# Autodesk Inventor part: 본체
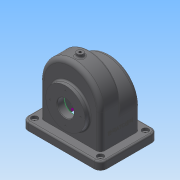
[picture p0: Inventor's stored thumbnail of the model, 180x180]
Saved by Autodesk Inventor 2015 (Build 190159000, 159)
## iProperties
Created: 2017-11
Part Number: 본체
Material: 알루미늄 6061
Document SubType Name: Modeling
Designer: user
Density: 2.7 g/cm^3
Appearance: 연회색
Mass: 1083.79 g
Surface Area: 1185.38 cm^2
Volume: 401.404 cm^3
Author: user
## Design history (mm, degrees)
sketch "스케치1"
  geometry: L1 (-58, 15)-(-58, -65); L2 (-58, -65)-(58, -65); L3 (58, -65)-(58, 15); C1 r 37.5 at (0, 0); A1 r 58 centre (0, 15) between (58, 15) and (-58, 15)
  constraints: 6 end point, 2 centre point, 2 point on circle, 1 perpendicular, 1 tangent, 1 vertical
extrude "돌출1" new body sketch "스케치1" distance "d18" = 9; taper "d19" = 0 deg
extrude "돌출2" join sketch "스케치1" distance "d20" = 38; taper "d21" = 0 deg
node "작업 평면1"
sketch "스케치2"
  geometry: C1 r 31 at (0, 0); 1 further point
  constraints: 1 centre point, 1 coincident
extrude "돌출3" join sketch "스케치2" distance "d30" = 10; taper "d31" = 0 deg
sketch "스케치3"
  geometry: L1 (58, -8)-(58, -65); L2 (58, -65)-(-58, -65); L3 (-58, -65)-(-58, -8); A1 r 58 centre (0, -8) between (58, -8) and (-58, -8); 1 further point
  constraints: 6 end point, 2 point on circle, 1 centre point, 1 perpendicular, 1 vertical
extrude "돌출4" join sketch "스케치3" distance "d39" = 38; taper "d40" = 0 deg
sketch "스케치4"
  geometry: C1 r 37.5 at (0, 0) reference; C2 r 16 at (0, 0)
  constraints: 1 centre point, 1 coincident
  dimensions: "d41" = 32 diameter of C2
extrude "돌출5" cut sketch "스케치4" distance "d42" = 14; taper "d43" = 0 deg
sketch "스케치5"
  geometry: L1 (-53, 14.446)-(-53, -65.554); L2 (53, 14.446)-(53, -65.554); L3 (-53, -65.554)-(53, -65.554); C1 r 16 at (0, 0) reference; A1 r 53 centre (0, 14.446) between (53, 14.446) and (-53, 14.446); A2 r 53 centre (0, -8.554) between (53, -8.554) and (-53, -8.554)
  constraints: 6 end point, 4 point on circle, 2 centre point, 2 point on line, 2 tangent, 2 vertical, 1 horizontal
extrude "돌출6" cut sketch "스케치5" distance "d49" = 66; taper "d50" = 0 deg
extrude "돌출7" cut sketch "스케치5" distance "d51" = 28; taper "d52" = 0 deg
extrude "돌출8" cut sketch "스케치5" distance "d53" = 95; taper "d54" = 0 deg
sketch "스케치6"
  geometry: L1 (133, 17)-(-17, 17); L2 (-17, 17)-(-17, -93); L3 (-17, -93)-(133, -93); L4 (133, 17)-(133, -93); L5 (-17, 17)-(-17, 5); L6 (-17, 17)-(-5, 17); L7 (133, -93)-(133, -81); L8 (133, -93)-(121, -93); L9 (116, 0)-(0, 0); L10 (0, 0)-(0, -76); L11 (0, -76)-(116, -76); L12 (116, -76)-(116, 0); L13 (111, -5)-(5, -5); L14 (5, -5)-(5, -71); L15 (5, -71)-(111, -71); L16 (111, -71)-(111, -5); C1 r 6 at (121, 5); C2 r 6 at (121, -81); C3 r 6 at (-5, -81); C4 r 6 at (-5, 5); C5 r 2.5 at (121, 5); C6 r 2.5 at (121, -81); C7 r 2.5 at (-5, -81); C8 r 2.5 at (-5, 5); 1 further point
  constraints: 32 end point, 8 centre point, 4 coincident, 4 parallel, 4 point on line, 3 perpendicular, 2 horizontal, 1 vertical
  dimensions: "d69" = 5 diameter of C5; "d70" = 5 diameter of C6; "d71" = 5 diameter of C7; "d72" = 5 diameter of C8
extrude "돌출15" join sketch "스케치6" distance "d86" = 15; taper "d87" = 0 deg
extrude "돌출16" join sketch "스케치6" distance "d88" = 10; taper "d89" = 0 deg
extrude "돌출17" join sketch "스케치6" distance "d90" = 10; taper "d91" = 0 deg
node "작업 평면3"
sketch "스케치8"
  geometry: C1 r 6 at (75, -36); 1 further point
  constraints: 1 centre point
  dimensions: "d95" = 12 diameter of C1
extrude "돌출18" join sketch "스케치8" stored distance "d96" = 0; taper "d97" = 0 deg
hole "구멍1" sketch "스케치8" diameter "d98" = 4.459; stored, may be unused: countersink angle "d102" = 82 deg, drill point angle "d104" = 118 deg; dims "d99" = 10, "d100" = 3.023, "d101" = 2, "d103" = 12.8
sketch "스케치9"
  geometry: L1 (0, 29)-(0, -29); L2 (-29, 0)-(29, 0); C1 r 37.5 at (0, 0) reference; A1 r 29 centre (0, 0) between (0, 29) and (0, -29)
  constraints: 4 end point, 4 point on circle, 1 centre point, 1 coincident, 1 perpendicular, 1 vertical
  dimensions: "d105" = 58 diameter of A1
hole "구멍2" sketch "스케치9" at (0, 29), (-29, 0), (29, 0), (0, -29) diameter "d106" = 2.459; stored, may be unused: countersink angle "d110" = 82 deg, drill point angle "d112" = 118 deg; dims "d107" = 6, "d108" = 3.023, "d109" = 2, "d111" = 8
sketch "스케치10"
  geometry: L1 (0, 26)-(0, -26); L2 (-26, 0)-(26, 0); C1 r 31 at (0, 0) reference; A1 r 26 centre (0, 0) between (0, 26) and (0, -26)
  constraints: 4 end point, 4 point on circle, 1 centre point, 1 coincident, 1 perpendicular, 1 vertical
  dimensions: "d113" = 52 diameter of A1
hole "구멍3" sketch "스케치10" at (0, 26), (-26, 0), (26, 0), (0, -26) diameter "d114" = 2.459; stored, may be unused: countersink angle "d118" = 82 deg, drill point angle "d120" = 118 deg; dims "d115" = 6, "d116" = 3.023, "d117" = 2, "d119" = 8
sketch "스케치11" dims "d51" = 28
  geometry: L1 (93, -80)-(-17, -80) reference; L2 (-7.073, -36.398)-(83.073, -36.398); L3 (83.073, -36.398)-(83.073, -43.602); L4 (83.073, -43.602)-(-7.073, -43.602); L5 (-7.073, -43.602)-(-7.073, -36.398); 1 further point
  constraints: 2 other
feature "엠보싱1" sketch "스케치11" dims "d125" = 0.5, "d126" = 0
fillet "모깎기1" dims "d127" = 3
fillet "모깎기2" dims "d128" = 8
fillet "모깎기3" dims "d129" = 12
fillet "모깎기4" dims "d130" = 3
chamfer "모따기1" distance "d131" = 1; stored, may be unused: second distance "d132" = 2, angle "d133" = 45 deg
chamfer "모따기2" distance "d134" = 1; stored, may be unused: second distance "d135" = 2, angle "d136" = 45 deg
fillet "모깎기5" dims "d137" = 3
node "솔리드1"
other parameters: "d22" = 48, "d26" = 116, "d92" = -144
